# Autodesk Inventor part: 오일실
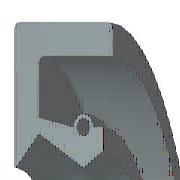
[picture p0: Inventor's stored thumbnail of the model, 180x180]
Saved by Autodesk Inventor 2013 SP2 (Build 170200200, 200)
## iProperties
IsCustomPart: 1
Created: 2009-02
Part Number: 오일실
Material: 고무
Description: 오일-실
Document SubType Name: Modeling
Standard: KS B 2804
Designer: SeoGD™[esajin.kr]
Standards Organization: KS
Language: ko-KR
Size Designation: D - 15 25 7
Categories: <MemberInstance><Categories><Category DisplayName="샤프트 부품" InternalName="7f7aeb1f-a693-4053-b835-cee3144e0d98" Mnemonic="SHFT"><Category DisplayName="실링" Intern
Density: 0.93 g/cm^3
Author: SeoGD™[esajin.kr]
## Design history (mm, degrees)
revolve "본체" stored, may be unused: angle "d17" = 90 deg
revolve "스프링1" stored, may be unused: angle "d18" = 90 deg
body "Solid1"
sketch "스케치1"
  geometry: L1 (0, 12.5)-(7, 12.5); L2 (7, 10.75)-(1.75, 10.75); L3 (1.75, 9.25)-(4.9, 7.5); L4 (4.9, 7.5)-(0, 7.5); L5 (0, 0)-(9.586, 0) reference; L6 (4.9, 7.5)-(6.3, 8.375); L7 (0, 18)-(0, -3) reference; L8 (-1.941, 0)-(11.507, 0) reference; L9 (4.2, 9.6)-(1.75, 10.09); L10 (1.75, 10.09)-(1.75, 10.75); L11 (0, 12.5)-(0, 7.588); L12 (4.9, 7.5)-(0, 7.5); L13 (1.75, 9.25)-(0.152, 7.528); L14 (7, 12.5)-(7, 10.75); L15 (5.6, 9.6)-(6.3, 9.6); L16 (6.3, 9.6)-(6.3, 8.375); C1 r 0.455 at (4.9, 9.6); A1 r 0.7 centre (4.9, 9.6) between (5.6, 9.6) and (4.2, 9.6); A2 r 0.088 centre (0.088, 7.588) between (0, 7.588) and (0.152, 7.528); 1 further point
  constraints: 28 end point, 5 horizontal alignment, 5 point on line, 4 point on circle, 4 vertical alignment, 3 centre point, 3 tangent, 2 collinear, 2 horizontal, 2 perpendicular, 1 coincident, 1 parallel
  dimensions: "d0" = 25 diameter of L1 L5 (= SD2); "d1" = 1.75 distance of L1.end L2.start (= SD); "d2" = 0.91 diameter of C1 (= SPDI); "d3" = 1.4 diameter of A1 (= SPDA); "d4" = 15 diameter of L3.end L5 (= NND); "d5" = 18.5 diameter of L3.start L5 (= TKDM); "d7" = 20.18 diameter of L9.end L5 (= TKDM + 0.24 x SWDT); "d8" = 1.75 distance between parallel lines of L11 L10 (= SD); "d9" = 4.9 distance from line of L11 C1.centre (= SPDST); "d10" = 19.2 diameter of C1.centre L5 (= HLDM); "d11" = 0.0875 radius of A2 (= 0.25 x LAB); "d12" = 6.3 distance between parallel lines of L11 L16 (= SDI); "d13" = 16.75 diameter of L6.end L5 (= ABDM); "d14" = 7 distance from line of L11 L1.end (= SWDT)
fillet "모깎기1" dims "d6" = 0.3 (= RR)
other parameters: "SD2" = 25 [user parameter; used in 1 equation term], "SWDT" = 7 [user parameter; used in 2 equation terms], "RR" = 0.3 [user parameter; used in 1 equation term], "SD" = 1.75 [user parameter; used in 2 equation terms], "NND" = 15 [user parameter; used in 1 equation term], "SPDA" = 1.4 [user parameter; used in 1 equation term], "SPDI" = 0.91 [user parameter; used in 1 equation term], "TKDM" = 18.5 [user parameter; used in 2 equation terms], "HLDM" = 19.2 [user parameter; used in 1 equation term], "ABDM" = 16.75 [user parameter; used in 1 equation term], "SDI" = 6.3 [user parameter; used in 1 equation term], "SPDST" = 4.9 [user parameter; used in 1 equation term], "LAB" = 0.35 [user parameter; used in 1 equation term], "d15" = 0, "d16" = 0, "d19" = 0
